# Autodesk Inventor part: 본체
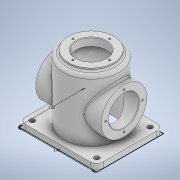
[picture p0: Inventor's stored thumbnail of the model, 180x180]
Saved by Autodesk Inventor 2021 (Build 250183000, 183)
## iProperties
Created: 2021-02
Part Number: 본체
Material: 알루미늄 6061
Document SubType Name: Modeling
Designer: mdu2-97
Density: 2.7 g/cm^3
Appearance: 기본값
Author: mdu2-97
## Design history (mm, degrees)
sketch "스케치1"
  geometry: L1 (-70, -60)-(70, -60); L2 (70, -60)-(70, 60); L3 (70, 60)-(-70, 60); L4 (-70, 60)-(-70, -60); L5 (-70, -60)-(70, 60); L6 (70, -60)-(-70, 60); 1 further point
  constraints: 12 end point, 2 midpoint, 2 parallel, 1 horizontal, 1 perpendicular
  dimensions: "d0" = 140 distance of L3.end L2.end; "d1" = 120 distance of L2.end L1.end
extrude "돌출1" new body sketch "스케치1" distance "d2" = 10; taper "d3" = 0 deg
sketch "스케치2"
  geometry: 1 further point
sketch "스케치3"
  geometry: C1 r 50 at (0, 0); 1 further point
  constraints: 1 centre point, 1 coincident
  dimensions: "d4" = 100 diameter of C1
extrude "돌출2" join sketch "스케치3" distance "d5" = 111; taper "d6" = 0 deg
sketch "스케치6"
  geometry: 1 further point
sketch "스케치7"
  geometry: C1 r 27 at (0, 0); 1 further point
  constraints: 1 centre point, 1 coincident
  dimensions: "d12" = 54 diameter of C1
extrude "돌출4" cut sketch "스케치7" distance "d13" = 9; taper "d14" = 0 deg
sketch "스케치8"
  geometry: C1 r 42 at (0, 0); 1 further point
  constraints: 1 centre point, 1 coincident
  dimensions: "d15" = 84 diameter of C1
extrude "돌출5" cut sketch "스케치8" extent not by distance; stored distance "d16" = 0; taper "d17" = 0 deg
sketch "스케치9"
  geometry: C1 r 41 at (0, 0); 1 further point
  constraints: 1 centre point, 1 coincident
  dimensions: "d18" = 82 diameter of C1
extrude "돌출6" join sketch "스케치9" distance "d19" = 5; taper "d20" = 0 deg
sketch "스케치10"
  geometry: C1 r 27 at (0, 0) reference; 1 further point
extrude "돌출7" cut sketch "스케치10" extent not by distance; stored distance "d21" = 5; taper "d22" = 0 deg
fillet "모깎기1" dims "d23" = 6
fillet "모깎기2" dims "d24" = 3
node "작업 평면1"
sketch "스케치11"
  geometry: L1 (10, 60)-(10, -60) reference; L2 (126, -41)-(126, 41) reference; L3 (0, 60)-(0, -60) reference; L4 (10, 50)-(10, -50) reference; L5 (115, -50)-(115, 50) reference; L6 (115, 0)-(10, 0); C1 r 41 at (60, 0); 1 further point
  constraints: 2 end point, 2 midpoint, 1 centre point, 1 point on line
  dimensions: "d26" = 82 diameter of C1; "d27" = 60 distance from line of C1.centre L3
extrude "돌출8" join sketch "스케치11" stored distance "d28" = 5; taper "d29" = 0 deg
sketch "스케치12"
  geometry: C1 r 27 at (0, 0); C2 r 41 at (0, 0) reference; 1 further point
  constraints: 1 centre point, 1 coincident
  dimensions: "d30" = 54 diameter of C1
extrude "돌출9" cut sketch "스케치12" stored distance "d31" = 5; taper "d32" = 0 deg
fillet "모깎기3" dims "d33" = 3
sketch "스케치13"
  geometry: 1 further point
fillet "모깎기4" dims "d34" = 12
sketch "스케치14"
  geometry: C1 r 4.5 at (-58, -48); A1 r 12 centre (-58, -48) between (-70, -48) and (-58, -60) reference; A2 r 12 centre (-58, 48) between (-58, 60) and (-70, 48) reference; A3 r 12 centre (58, 48) between (70, 48) and (58, 60) reference; A4 r 12 centre (58, -48) between (58, -60) and (70, -48) reference; 1 further point
  constraints: 1 centre point, 1 coincident
  dimensions: "d35" = 9 diameter of C1
extrude "돌출10" cut sketch "스케치14" extent not by distance; stored distance "d36" = 0; taper "d37" = 0 deg
sketch "스케치15" dims "d38" = 66
  geometry: 3 further points
  constraints: 1 vertical alignment, 2 other
hole "구멍1" sketch "스케치15" at (0, 33) diameter "d39" = 3.242; stored, may be unused: countersink angle "d43" = 90 deg, drill point angle "d45" = 118 deg; dims "d40" = 8, "d41" = 12, "d42" = 2, "d44" = 10
sketch "스케치16" dims "d49" = 66
  geometry: 3 further points
  constraints: 1 coincident, 1 vertical alignment, 2 other
hole "구멍2" sketch "스케치16" at (0, 33) diameter "d50" = 3.242; stored, may be unused: countersink angle "d54" = 90 deg, drill point angle "d56" = 118 deg; dims "d51" = 8, "d52" = 12, "d53" = 2, "d55" = 10
fillet "모깎기5" dims "d60" = 3
chamfer "모따기1" distance "d61" = 1; stored, may be unused: second distance "d62" = 2, angle "d63" = 45 deg
sketch "스케치17"
  geometry: 1 further point
node "솔리드1"
mirror "미러1"
mirror "미러2"
mirror "미러3"
pattern_circular "원형 패턴1" dims angle "d47" = 360 deg
mirror "미러4"
pattern_circular "원형 패턴2" dims angle "d58" = 360 deg
node "투영된 루프1"
node "작업 평면2"
node "투영된 루프2"
feature "A9D066F2-1C7D-4E18-AEED-F7BC21143FA4" dims "d39" = 3.242, "d40" = 8, "d41" = 12, "d42" = 2, "d43" = 90 deg, "d44" = 10, "d45" = 118 deg
other parameters: "d25" = 59
